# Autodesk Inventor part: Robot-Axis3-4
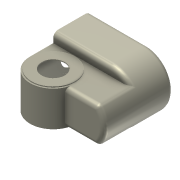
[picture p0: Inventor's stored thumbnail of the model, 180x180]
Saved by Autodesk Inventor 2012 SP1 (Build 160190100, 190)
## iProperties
Shininess: 21.0
Length Units: 11269
Angle Units: 11279
Time Units: 11290
Mass Units: 11283
Length Display Precision: 3
Angle Display Precision: 2
Created: 2001-08
Part Number: Robot-Axis3-4
Document SubType Name: ﾓﾃﾞﾘﾝｸﾞ
Designer: Administrator
Density: 1 g/cm^3
Material: Default
Density: 0.0
Volumn: 0.0
Area: 0.0
PropertySet Name: Model Information
Control State: 0
Master: False
Checked Out: False
Author: Administrator
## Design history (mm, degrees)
sketch "ｽｹｯﾁ1"
  geometry: L1 (-50, 0)-(-50, 68.315); L2 (130, 50)-(-50, 50); L3 (50, 0)-(50, 50); L4 (130, 50)-(130, -20); L5 (45.826, -20)-(130, -20); A1 r 50 centre (0, 0) between (-50, 0) and (50, 0); 1 further point
  constraints: 10 end point, 3 perpendicular, 3 point on circle, 3 tangent, 2 point on line, 1 centre point, 1 coincident, 1 parallel, 1 vertical, 1 other
  dimensions: "d0" = 100 diameter of A1; "d10" = 20 distance from line of L5 A1.centre; "d11" = 180 distance between parallel lines of L4 L1
extrude "押し出し1" new body sketch "ｽｹｯﾁ1" stored distance "d1" = 76; taper "d2" = 0 deg
sketch "ｽｹｯﾁ2"
  geometry: C1 r 50 at (0, 0) reference; C2 r 47 at (0, 0)
  constraints: 1 centre point
  dimensions: "d3" = 3 radial gap between concentric circles of C1 C2
extrude "押し出し2" join sketch "ｽｹｯﾁ2" distance "d4" = 2; taper "d5" = 0 deg
sketch "ｽｹｯﾁ3"
  geometry: L1 (-50, 50)-(-50, 130); L2 (-50, 130)-(130, 130); L3 (-53.41, 90)-(-7.321, 90); L4 (130, 50)-(-50, 50) reference; L5 (-50, 50)-(130, 50); L6 (130, 50)-(130, 130); C1 r 50 at (0, 0) reference
  constraints: 10 end point, 1 collinear, 1 parallel, 1 perpendicular, 1 tangent, 1 vertical
  dimensions: "d6" = 90 distance from line of L3 C1.centre; "d7" = 40 distance between parallel lines of L3 L2; "d8" = 180 distance of L1.end L2.end
extrude "押し出し3" join sketch "ｽｹｯﾁ3" stored distance "d12" = 116; taper "d13" = 0 deg
sketch "ｽｹｯﾁ4"
  geometry: L1 (-20, 130)-(96, 130) reference; L2 (0, 0)-(76, 0) reference; L3 (-37.109, 90)-(114.915, 90); L4 (38, 130)-(38, 36.926); C1 r 37 at (38, 90)
  constraints: 4 end point, 2 point on line, 1 centre point, 1 midpoint, 1 parallel, 1 perpendicular
  dimensions: "d14" = 90 distance between parallel lines of L3 L2; "d15" = 74 diameter of C1
extrude "押し出し4" join sketch "ｽｹｯﾁ4" distance "d16" = 1; taper "d17" = 0 deg
fillet "Chamfer1" dims "d18" = 58
fillet "Chamfer2" dims "d19" = 10
fillet "Chamfer3" dims "d20" = 10
shell "Shell1" dims "d28" = 2
sketch "Sketch5"
  geometry: C1 r 47 at (0, 0) reference
hole "Hole1" sketch "Sketch5" at (0, 0) diameter "d21" = 50; stored, may be unused: countersink angle "d25" = 82 deg, drill point angle "d27" = 118 deg; dims "d22" = 6, "d23" = 4, "d24" = 2, "d26" = 2
sketch "Sketch6"
  geometry: C1 r 37 at (0, 0) reference
hole "Hole2" sketch "Sketch6" at (0, 0) diameter "d29" = 50; stored, may be unused: countersink angle "d33" = 82 deg, drill point angle "d35" = 118 deg; dims "d30" = 6, "d31" = 4, "d32" = 2, "d34" = 2
body "Solid1"
mirror "Mirror1"
